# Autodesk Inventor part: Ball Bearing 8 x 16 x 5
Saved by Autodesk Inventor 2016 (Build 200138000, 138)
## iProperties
Created: 2016-03
Part Number: Ball Bearing 8 x 16 x 5
Material: Generic
Document SubType Name: Modeling
Designer: bongo_000
Density: 1 g/cm^3
Appearance: Default
Author: bongo_000
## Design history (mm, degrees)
feature "REVOLVE1"
body "Solid1"
